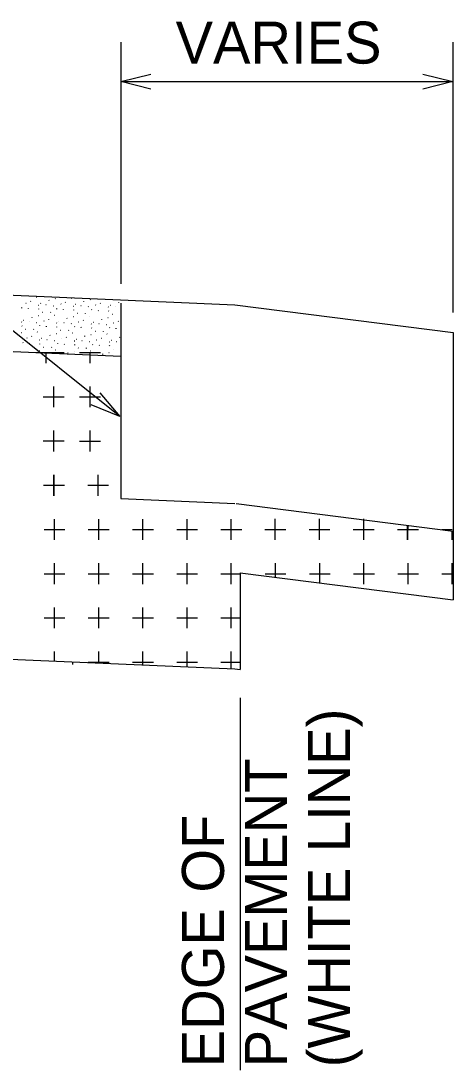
# Model space of a CAD drawing. Extents: x -28.8 to 41.7, y 0 to 25.4.
# Drawn here: x 12.616 to 14.057, y 5.997 to 9.495 of the extents above; entities that cross this region are included whole.
import ezdxf

# ---------------------------------------------------------------- set-up
doc = ezdxf.new("R2010")
doc.units = 0
doc.layers.add('Default', color=7, linetype='Continuous')

msp = doc.modelspace()

# ---------------------------------------------------------------- linework, layer by layer
at = {"layer": 'Default'}
for p, q in [((12.9492, 9.4248), (12.9492, 8.6186)), ((14.0568, 9.4248), (14.0568, 8.5231)), ((12.9492, 9.2931), (14.0568, 9.2931)), ((12.9455, 8.1762), (12.0498, 8.8929)), ((12.6671, 8.5743), (12.6681, 8.5742)), ((12.7833, 8.5712), (12.7845, 8.571)), ((12.6196, 8.538), (12.6191, 8.5393)), ((12.6325, 8.5547), (12.6335, 8.5545)), ((12.6416, 8.5353), (12.6411, 8.5367)), ((12.6476, 8.5607), (12.6486, 8.5597)), ((12.6746, 8.548), (12.6758, 8.5478)), ((12.681, 8.5538), (12.682, 8.5535)), ((12.6995, 8.5497), (12.7005, 8.5493)), ((12.7101, 8.5628), (12.7095, 8.5642)), ((12.7241, 8.5458), (12.7251, 8.5457)), ((12.7301, 8.5692), (12.7313, 8.569)), ((12.736, 8.5347), (12.7355, 8.5362)), ((12.7486, 8.5515), (12.7498, 8.5513)), ((12.7638, 8.5573), (12.765, 8.5563)), ((12.791, 8.5447), (12.792, 8.5445)), ((12.7971, 8.5505), (12.7983, 8.5503)), ((12.8156, 8.5463), (12.8168, 8.5462)), ((12.8263, 8.5595), (12.8258, 8.5608)), ((12.8405, 8.5427), (12.8415, 8.5423)), ((12.8465, 8.566), (12.8475, 8.5658)), ((12.865, 8.5482), (12.866, 8.548)), ((12.8801, 8.554), (12.8813, 8.5532)), ((12.9071, 8.5415), (12.9083, 8.5413)), ((12.9135, 8.5473), (12.9146, 8.547)), ((12.932, 8.5432), (12.933, 8.5428)), ((12.9425, 8.5562), (12.942, 8.5575)), ((12.9492, 8.5537), (12.9492, 7.9027)), ((12.6535, 8.5063), (12.653, 8.5077)), ((12.6736, 8.5127), (12.6746, 8.5125)), ((12.6763, 8.5338), (12.6758, 8.5353)), ((12.6873, 8.5242), (12.6883, 8.524)), ((12.7155, 8.5228), (12.715, 8.5243)), ((12.7268, 8.5147), (12.728, 8.5143)), ((12.758, 8.532), (12.7575, 8.5335)), ((12.7698, 8.503), (12.7693, 8.5043)), ((12.79, 8.5095), (12.791, 8.5093)), ((12.7925, 8.5307), (12.792, 8.532)), ((12.8036, 8.5208), (12.8046, 8.5207)), ((12.8316, 8.5197), (12.8311, 8.521)), ((12.8431, 8.5113), (12.8441, 8.5112)), ((12.8523, 8.5315), (12.8518, 8.5328)), ((12.8743, 8.5288), (12.8738, 8.5302)), ((12.8861, 8.4997), (12.8856, 8.5012)), ((12.9061, 8.5062), (12.9071, 8.506)), ((12.9088, 8.5273), (12.9083, 8.5288)), ((12.9198, 8.5177), (12.921, 8.5173)), ((12.6181, 8.4915), (12.6193, 8.4913)), ((12.6198, 8.4773), (12.6193, 8.4787)), ((12.6245, 8.4973), (12.6256, 8.4972)), ((12.6308, 8.4677), (12.632, 8.4675)), ((12.643, 8.4932), (12.644, 8.493)), ((12.659, 8.4665), (12.6585, 8.4678)), ((12.6676, 8.4893), (12.6688, 8.4892)), ((12.6795, 8.4782), (12.679, 8.4795)), ((12.6921, 8.495), (12.6931, 8.4948)), ((12.7015, 8.4755), (12.701, 8.477)), ((12.7075, 8.5008), (12.7085, 8.5)), ((12.7345, 8.4883), (12.7355, 8.488)), ((12.7361, 8.4742), (12.7356, 8.4755)), ((12.7408, 8.494), (12.7418, 8.4938)), ((12.7591, 8.4898), (12.7601, 8.4897)), ((12.784, 8.486), (12.785, 8.4858)), ((12.7956, 8.475), (12.7951, 8.4763)), ((12.8085, 8.4918), (12.8095, 8.4915)), ((12.8178, 8.4723), (12.8171, 8.4737)), ((12.8236, 8.4975), (12.8246, 8.4967)), ((12.8508, 8.485), (12.8518, 8.4847)), ((12.8523, 8.4708), (12.8518, 8.4722)), ((12.857, 8.4908), (12.8581, 8.4907)), ((12.8755, 8.4865), (12.8765, 8.4863)), ((12.9001, 8.4828), (12.9011, 8.4827)), ((12.912, 8.4717), (12.9115, 8.473)), ((12.9246, 8.4885), (12.9258, 8.4883)), ((12.934, 8.469), (12.9335, 8.4705)), ((12.94, 8.4943), (12.941, 8.4935)), ((12.6171, 8.4563), (12.6181, 8.456)), ((12.6356, 8.4385), (12.6368, 8.4383)), ((12.6508, 8.4443), (12.652, 8.4435)), ((12.6703, 8.4582), (12.6715, 8.458)), ((12.678, 8.4318), (12.679, 8.4315)), ((12.6843, 8.4375), (12.6853, 8.4373)), ((12.7026, 8.4333), (12.7038, 8.4332)), ((12.7133, 8.4465), (12.7128, 8.4478)), ((12.7335, 8.453), (12.7345, 8.4528)), ((12.7471, 8.4643), (12.7481, 8.4642)), ((12.752, 8.4352), (12.753, 8.435)), ((12.7671, 8.441), (12.7683, 8.4402)), ((12.7753, 8.4632), (12.7748, 8.4645)), ((12.7866, 8.4548), (12.7876, 8.4547)), ((12.8005, 8.4343), (12.8016, 8.434)), ((12.8296, 8.4432), (12.829, 8.4447)), ((12.8496, 8.4497), (12.8508, 8.4495)), ((12.8633, 8.4612), (12.8645, 8.461)), ((12.8681, 8.432), (12.8691, 8.4318)), ((12.8835, 8.4378), (12.8845, 8.437)), ((12.8915, 8.46), (12.891, 8.4613)), ((12.9028, 8.4515), (12.904, 8.4513)), ((12.9168, 8.431), (12.9178, 8.4308)), ((12.9458, 8.44), (12.9453, 8.4413)), ((14.0569, 8.4567), (14.0569, 7.7939)), ((12.623, 8.4217), (12.6225, 8.4232)), ((12.645, 8.4192), (12.6445, 8.4205)), ((12.677, 8.3965), (12.678, 8.3963)), ((12.6795, 8.4177), (12.679, 8.419)), ((12.6906, 8.4078), (12.6916, 8.4077)), ((12.7188, 8.4067), (12.7181, 8.408)), ((12.7273, 8.4297), (12.7285, 8.4293)), ((12.7301, 8.3983), (12.7313, 8.3982)), ((12.7393, 8.4185), (12.7388, 8.4198)), ((12.7611, 8.4158), (12.7606, 8.4172)), ((12.7941, 8.4285), (12.7953, 8.4283)), ((12.7958, 8.4143), (12.7953, 8.4158)), ((12.807, 8.4047), (12.808, 8.4043)), ((12.819, 8.4302), (12.82, 8.4298)), ((12.835, 8.4033), (12.8345, 8.4048)), ((12.8436, 8.4263), (12.8448, 8.4262)), ((12.8555, 8.4152), (12.855, 8.4167)), ((12.8775, 8.4125), (12.877, 8.4138)), ((12.9105, 8.4252), (12.9116, 8.425)), ((12.9121, 8.411), (12.9116, 8.4125)), ((12.9231, 8.4013), (12.9241, 8.4012)), ((12.9351, 8.4268), (12.9363, 8.4267)), ((12.6566, 8.3903), (12.6563, 8.3913)), ((12.6653, 8.3892), (12.7001, 8.3892)), ((12.6912, 8.3892), (12.7607, 8.3892)), ((12.7001, 8.3544), (12.7001, 8.3892)), ((12.7001, 8.3892), (12.7348, 8.3892)), ((12.7731, 8.3868), (12.7726, 8.3882)), ((12.7931, 8.3932), (12.7941, 8.393)), ((12.8119, 8.3892), (12.8467, 8.3892)), ((12.8465, 8.3952), (12.8475, 8.3948)), ((12.8467, 8.3544), (12.8467, 8.3892)), ((12.8467, 8.3892), (12.8814, 8.3892)), ((12.8893, 8.3835), (12.8888, 8.3848)), ((12.9093, 8.39), (12.9105, 8.3898)), ((12.9431, 8.378), (12.9433, 8.3778)), ((12.7254, 8.2069), (12.7254, 8.2764)), ((12.726, 8.2417), (12.726, 8.2764)), ((12.8467, 8.2069), (12.8467, 8.2764)), ((12.6906, 8.2417), (12.7601, 8.2417)), ((12.726, 8.2069), (12.726, 8.2417)), ((12.726, 8.2417), (12.7607, 8.2417)), ((12.8119, 8.2417), (12.8814, 8.2417)), ((12.7254, 8.0603), (12.7254, 8.1298)), ((12.726, 8.0596), (12.726, 8.1291)), ((12.8467, 8.0942), (12.8467, 8.1291)), ((12.6906, 8.0951), (12.7601, 8.0951)), ((12.8119, 8.0942), (12.8467, 8.0942)), ((12.8467, 8.0596), (12.8467, 8.0942)), ((12.8467, 8.0942), (12.8814, 8.0942)), ((12.726, 7.9469), (12.726, 7.9816)), ((12.7268, 7.9121), (12.7268, 7.9816)), ((12.8734, 7.9121), (12.8734, 7.9816)), ((12.6912, 7.9469), (12.726, 7.9469)), ((12.6921, 7.9469), (12.7616, 7.9469)), ((12.726, 7.9121), (12.726, 7.9469)), ((12.726, 7.9469), (12.7607, 7.9469)), ((12.8387, 7.9469), (12.9082, 7.9469)), ((12.7279, 7.9121), (12.7279, 7.9122)), ((12.7279, 7.7994), (12.7279, 7.8342)), ((12.8754, 7.7647), (12.8754, 7.8342)), ((13.0228, 7.7994), (13.0228, 7.8342)), ((13.1703, 7.7647), (13.1703, 7.8342)), ((13.3176, 7.7994), (13.3176, 7.8342)), ((13.4644, 7.7651), (13.4644, 7.8346)), ((13.6119, 7.7999), (13.6119, 7.8346)), ((13.7593, 7.7651), (13.7593, 7.8346)), ((13.9054, 7.7647), (13.9054, 7.8131)), ((13.9073, 7.7994), (13.9073, 7.8129)), ((12.6933, 7.7994), (12.7279, 7.7994)), ((12.7279, 7.7647), (12.7279, 7.7994)), ((12.7279, 7.7994), (12.7626, 7.7994)), ((12.8406, 7.7994), (12.9101, 7.7994)), ((12.9881, 7.7994), (13.0228, 7.7994)), ((13.0228, 7.7647), (13.0228, 7.7994)), ((13.0228, 7.7994), (13.0576, 7.7994)), ((13.1354, 7.7994), (13.2049, 7.7994)), ((13.2829, 7.7994), (13.3176, 7.7994)), ((13.3176, 7.7647), (13.3176, 7.7994)), ((13.3176, 7.7994), (13.3524, 7.7994)), ((13.4298, 7.7999), (13.4993, 7.7999)), ((13.5771, 7.7999), (13.6119, 7.7999)), ((13.6119, 7.7651), (13.6119, 7.7999)), ((13.6119, 7.7999), (13.6466, 7.7999)), ((13.7244, 7.7999), (13.7939, 7.7999)), ((13.8719, 7.7999), (13.9066, 7.7999)), ((13.9066, 7.7651), (13.9066, 7.7999)), ((13.9066, 7.7999), (13.9414, 7.7999)), ((14.0199, 7.7999), (14.0546, 7.7999)), ((14.0546, 7.7647), (14.0546, 7.7942)), ((14.0569, 7.7939), (14.0569, 7.5651)), ((12.7279, 7.6174), (12.7279, 7.6869)), ((12.8754, 7.6521), (12.8754, 7.6869)), ((13.0228, 7.6174), (13.0228, 7.6869)), ((13.1703, 7.6521), (13.1703, 7.6869)), ((13.3176, 7.6174), (13.3176, 7.6869)), ((13.4651, 7.6521), (13.4651, 7.6869)), ((13.6124, 7.6212), (13.6124, 7.6869)), ((13.7598, 7.6521), (13.7598, 7.6869)), ((13.9073, 7.6174), (13.9073, 7.6869)), ((14.0546, 7.6521), (14.0546, 7.6869)), ((12.6933, 7.6521), (12.7626, 7.6521)), ((12.8406, 7.6521), (12.8754, 7.6521)), ((12.8754, 7.6174), (12.8754, 7.6521)), ((12.8754, 7.6521), (12.9101, 7.6521)), ((12.9881, 7.6521), (13.0576, 7.6521)), ((13.1354, 7.6521), (13.1703, 7.6521)), ((13.1703, 7.6174), (13.1703, 7.6521)), ((13.1703, 7.6521), (13.2049, 7.6521)), ((13.2829, 7.6521), (13.3474, 7.6521)), ((13.3474, 7.6549), (13.3474, 7.3321)), ((13.4303, 7.6521), (13.4651, 7.6521)), ((13.4651, 7.6401), (13.4651, 7.6521)), ((13.4651, 7.6521), (13.4998, 7.6521)), ((13.5778, 7.6521), (13.6473, 7.6521)), ((13.7251, 7.6521), (13.7598, 7.6521)), ((13.7598, 7.6174), (13.7598, 7.6521)), ((13.7598, 7.6521), (13.7946, 7.6521)), ((13.8724, 7.6521), (13.9419, 7.6521)), ((14.0199, 7.6521), (14.0546, 7.6521)), ((14.0546, 7.6174), (14.0546, 7.6521)), ((14.0546, 7.6521), (14.0569, 7.6521)), ((12.7279, 7.5047), (12.7279, 7.5394)), ((12.8754, 7.4699), (12.8754, 7.5394)), ((13.0228, 7.5047), (13.0228, 7.5394)), ((13.1703, 7.4699), (13.1703, 7.5394)), ((13.3176, 7.5047), (13.3176, 7.5394)), ((12.6933, 7.5047), (12.7279, 7.5047)), ((12.7279, 7.4699), (12.7279, 7.5047)), ((12.7279, 7.5047), (12.7626, 7.5047)), ((12.8406, 7.5047), (12.9101, 7.5047)), ((12.9881, 7.5047), (13.0228, 7.5047)), ((13.0228, 7.4699), (13.0228, 7.5047)), ((13.0228, 7.5047), (13.0576, 7.5047)), ((13.1354, 7.5047), (13.2049, 7.5047)), ((13.2829, 7.5047), (13.3176, 7.5047)), ((13.3176, 7.4699), (13.3176, 7.5047)), ((13.3176, 7.5047), (13.3474, 7.5047)), ((12.7279, 7.3604), (12.7279, 7.3921)), ((12.8754, 7.3572), (12.8754, 7.3921)), ((13.0228, 7.3477), (13.0228, 7.3921)), ((13.1703, 7.3572), (13.1703, 7.3921)), ((13.3176, 7.3349), (13.3176, 7.3921)), ((12.7893, 7.3491), (12.7893, 7.3551)), ((12.8406, 7.3572), (12.8754, 7.3572)), ((12.8754, 7.3541), (12.8754, 7.3572)), ((12.8754, 7.3572), (12.9101, 7.3572)), ((12.9881, 7.3572), (13.0576, 7.3572)), ((13.1354, 7.3572), (13.1703, 7.3572)), ((13.1703, 7.3412), (13.1703, 7.3572)), ((13.1703, 7.3572), (13.2049, 7.3572)), ((13.2829, 7.3572), (13.3474, 7.3572)), ((13.3474, 7.2386), (13.3474, 5.9969))]:
    msp.add_line(p, q, dxfattribs=at)
for points in [[(13.0495, 9.2681), (12.9492, 9.2931), (13.0495, 9.3182)], [(13.9566, 9.3182), (14.0568, 9.2931), (13.9566, 9.2681)], [(11.9283, 8.6096), (13.3289, 8.5489), (14.0569, 8.4567)], [(10.9749, 8.4631), (12.9492, 8.3775)], [(12.8795, 8.2556), (12.9455, 8.1762), (12.8499, 8.2151)], [(12.9492, 7.9027), (13.3289, 7.8862)], [(13.3338, 7.8861), (14.0569, 7.7944)], [(13.3474, 7.6549), (14.0569, 7.5651)], [(10.9749, 7.4364), (13.3289, 7.3344), (13.3474, 7.3321)]]:
    msp.add_lwpolyline(points, dxfattribs=at)

# ---------------------------------------------------------------- texts
msp.add_text('VARIES', height=0.14, dxfattribs=at).set_placement((13.1318, 9.3531))
for s, p in [('(WHITE LINE)', (13.7131, 6.006)), ('PAVEMENT', (13.5031, 6.006)), ('EDGE OF', (13.2931, 6.006))]:
    msp.add_text(s, height=0.14, rotation=90, dxfattribs=at).set_placement(p)

doc.saveas('drawing.dxf')
